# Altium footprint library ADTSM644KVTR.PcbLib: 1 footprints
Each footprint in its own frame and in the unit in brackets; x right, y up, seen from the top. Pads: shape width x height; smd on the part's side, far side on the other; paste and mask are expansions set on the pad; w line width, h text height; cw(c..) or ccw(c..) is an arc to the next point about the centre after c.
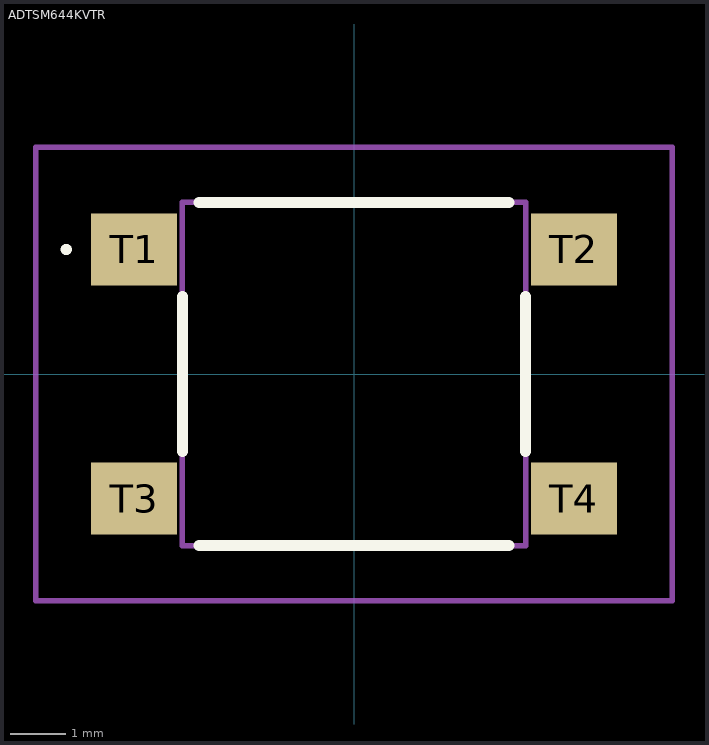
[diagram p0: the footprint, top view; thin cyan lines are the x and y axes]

## ADTSM644KVTR [mm]
pads (4):
  rect 1.55x1.3 smd: T1(-3.975,2.25) T2(3.975,2.25) T3(-3.975,-2.25) T4(3.975,-2.25)
Top Overlay:
  lines w0.1: -5.2,2.2 -5.2,2.2 ; -5.2,2.2 ccw(c-5.2,2.25) -5.2,2.3 ; -5.2,2.2 cw(c-5.2,2.25) -5.2,2.3 ; -5.2,2.3 -5.2,2.3
  lines w0.2: -3.1,-1.4 -3.1,1.4 ; -2.8,-3.1 2.8,-3.1 ; -2.8,3.1 2.8,3.1 ; 3.1,-1.4 3.1,1.4
Mechanical 15:
  lines w0.1: -3.1,-3.1 3.1,-3.1 3.1,3.1 -3.1,3.1 -3.1,-3.1
Mechanical 20:
  lines w0.1: -5.75,-4.1 5.75,-4.1 5.75,4.1 -5.75,4.1 -5.75,-4.1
